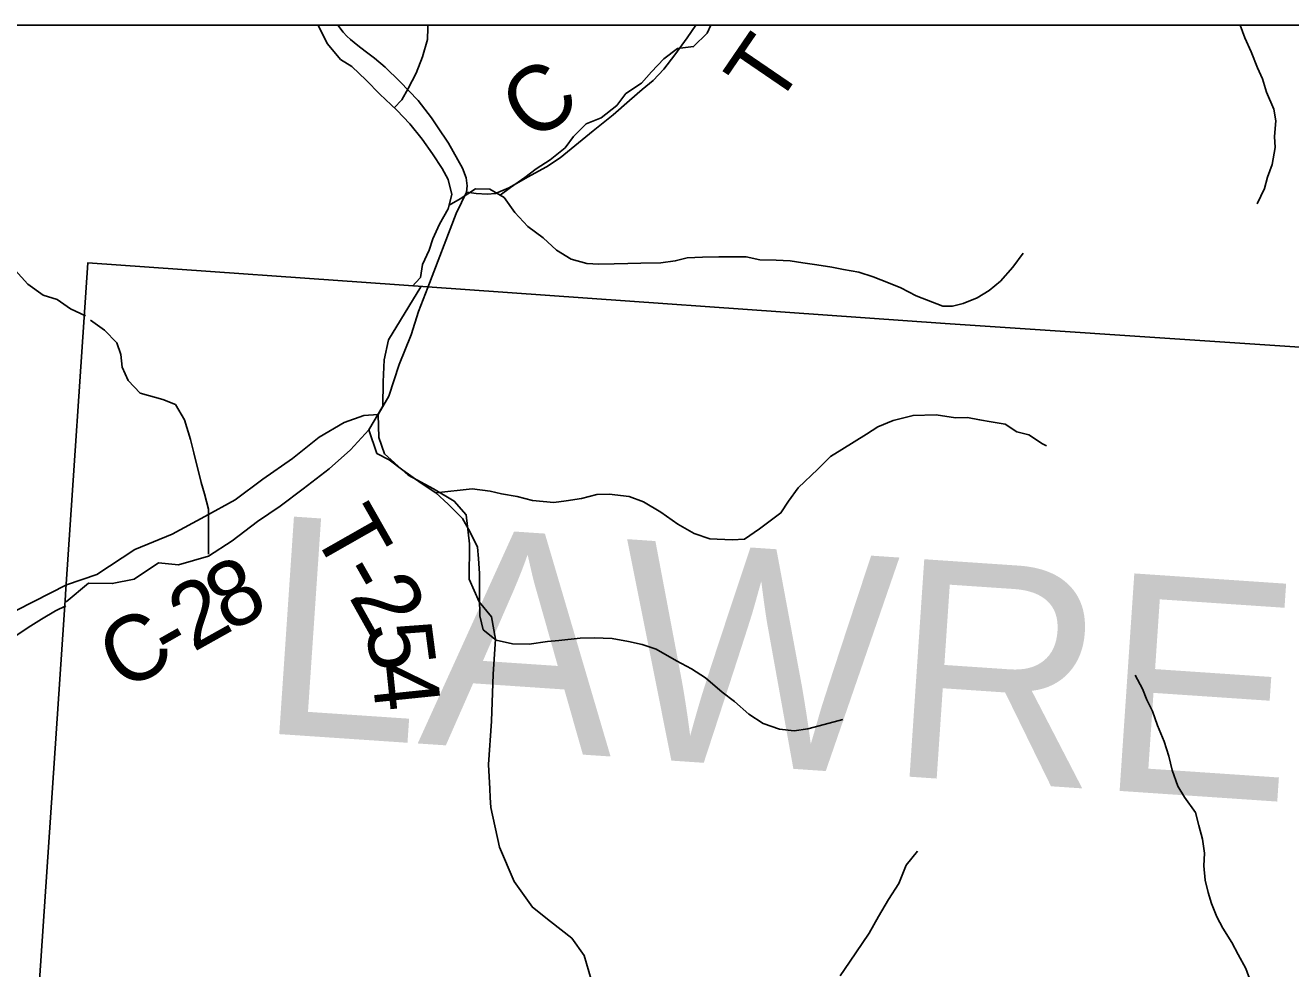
# Model space of a CAD drawing. Extents: x 0 to 34, y 0 to 22.
# Drawn here: x 3.511 to 4.61, y 20.08 to 20.9 of the extents above; entities that cross this region are included whole.
import ezdxf

# ---------------------------------------------------------------- set-up
doc = ezdxf.new("R2010")
doc.units = 0
for name, color, linetype in [('GM_X_County_Road', 7, 'Continuous'), ('GM_X_County_Road_Text', 7, 'Continuous'), ('GM_X_County_Text', 7, 'Continuous'), ('GM_X_Minor_River', 7, 'Continuous'), ('GM_X_Township_Road', 7, 'Continuous'), ('GM_X_Township_Road_Text', 7, 'Continuous'), ('GM_X_Unincorporated', 7, 'Continuous'), ('SH_Cut_Line', 7, 'Continuous')]:
    doc.layers.add(name, color=color, linetype=linetype)

msp = doc.modelspace()

# ---------------------------------------------------------------- linework, layer by layer
at = {"layer": 'GM_X_County_Road'}
for points in [[(3.8896, 20.746), (3.8941, 20.755), (3.8945, 20.7606), (3.8938, 20.7673), (3.8905, 20.7759), (3.8783, 20.7975), (3.8687, 20.8117), (3.8635, 20.8197), (3.852, 20.8345), (3.836, 20.8511), (3.8233, 20.8636), (3.8141, 20.8714), (3.8061, 20.8774), (3.7996, 20.8825), (3.7933, 20.8877), (3.79, 20.8906), (3.787, 20.894), (3.7822, 20.9)], [(3.8604, 20.6722), (3.885, 20.7363), (3.8896, 20.746)], [(3.5465, 20.4139), (3.573, 20.4229), (3.6059, 20.4444), (3.6382, 20.4578), (3.6668, 20.4731), (3.6931, 20.4877), (3.7171, 20.5057), (3.7427, 20.5237), (3.7659, 20.5421), (3.7877, 20.5548), (3.8048, 20.5608), (3.8173, 20.5618), (3.8265, 20.5777), (3.8355, 20.6053), (3.8459, 20.631), (3.8522, 20.6514), (3.8604, 20.6722)], [(3.4893, 20.3844), (3.5465, 20.4139)]]:
    msp.add_lwpolyline(points, dxfattribs=at)
at = {"layer": 'GM_X_Minor_River'}
for points in [[(3.8472, 20.6733), (3.8501, 20.6766), (3.8539, 20.6808), (3.8558, 20.6921), (3.8616, 20.7046), (3.8647, 20.7145), (3.8705, 20.7273), (3.8782, 20.7405), (3.8813, 20.753), (3.878, 20.7659), (3.8728, 20.7755), (3.8646, 20.7884), (3.8556, 20.801), (3.8447, 20.8144), (3.8334, 20.8262), (3.8188, 20.84), (3.8068, 20.8522), (3.7944, 20.8641), (3.7846, 20.8702), (3.7733, 20.884), (3.7681, 20.8939), (3.765, 20.9)], [(3.8313, 20.8282), (3.8377, 20.8353), (3.8434, 20.8451), (3.8504, 20.8583), (3.8558, 20.8727), (3.86, 20.8875), (3.8605, 20.8977), (3.8605, 20.9)], [(3.9232, 20.7524), (3.9321, 20.7591), (3.9446, 20.7677), (3.9545, 20.7752), (3.9667, 20.7831), (3.9797, 20.7936), (3.9869, 20.8034), (3.998, 20.8143), (4.0109, 20.8195), (4.0246, 20.8304), (4.0323, 20.8406), (4.046, 20.8496), (4.0548, 20.8594), (4.0654, 20.8707), (4.0773, 20.8797), (4.0913, 20.8815), (4.1031, 20.8931), (4.1063, 20.9)], [(4.566, 20.9), (4.5703, 20.8891), (4.5756, 20.8769), (4.5812, 20.8629), (4.5854, 20.8534), (4.5891, 20.842), (4.5955, 20.8271), (4.597, 20.8169), (4.5958, 20.8032), (4.5965, 20.7938), (4.5938, 20.779), (4.59, 20.768), (4.5873, 20.7581), (4.5808, 20.7449)], [(3.563, 20.6475), (3.5501, 20.6536), (3.5384, 20.6616), (3.5263, 20.6655), (3.5128, 20.6751), (3.5019, 20.6873), (3.4918, 20.6977), (3.479, 20.7114), (3.4707, 20.7213), (3.4602, 20.7339), (3.4516, 20.7469), (3.4396, 20.7584), (3.4318, 20.7706), (3.4311, 20.7827), (3.4312, 20.7956), (3.4309, 20.8059), (3.4321, 20.8165), (3.433, 20.8286), (3.4338, 20.8411)], [(3.879, 20.7436), (3.8885, 20.7492), (3.9018, 20.7578), (3.9143, 20.7577), (3.9267, 20.7504), (3.9361, 20.7374), (3.9473, 20.7252), (3.9605, 20.7152), (3.9721, 20.7045), (3.985, 20.6968), (3.9986, 20.6929), (4.0091, 20.6925), (4.0224, 20.6927), (4.0341, 20.693), (4.0455, 20.6933), (4.0629, 20.6935), (4.0754, 20.6953), (4.0857, 20.6979), (4.0989, 20.6986), (4.1133, 20.6988), (4.1371, 20.6987), (4.1489, 20.6963), (4.1629, 20.6958), (4.1753, 20.6953), (4.1863, 20.6937), (4.1984, 20.6917), (4.2113, 20.6897), (4.2215, 20.6878), (4.2347, 20.6854), (4.2472, 20.6815), (4.2607, 20.6761), (4.2713, 20.6718), (4.2845, 20.6649), (4.3077, 20.656)], [(4.3077, 20.656), (4.3161, 20.656), (4.3256, 20.6582), (4.3377, 20.6631), (4.348, 20.6695), (4.3579, 20.6775), (4.3685, 20.6899), (4.3776, 20.702)], [(3.5462, 20.399), (3.5657, 20.4151), (3.5862, 20.4149), (3.6052, 20.4186), (3.6265, 20.4329), (3.6439, 20.4312), (3.6698, 20.4386), (3.6903, 20.4521), (3.7124, 20.4687), (3.7322, 20.4822), (3.752, 20.4973), (3.7748, 20.5146), (3.7931, 20.5311), (3.8092, 20.5485), (3.8214, 20.5689), (3.8216, 20.5902), (3.8224, 20.6092), (3.8263, 20.6266), (3.8542, 20.6727)], [(3.5673, 20.6437), (3.5795, 20.6351), (3.5902, 20.6242), (3.5937, 20.614), (3.595, 20.603), (3.6, 20.5913), (3.6104, 20.5804), (3.6302, 20.5748), (3.6412, 20.5704), (3.649, 20.5572), (3.6541, 20.5401), (3.6572, 20.5284), (3.6635, 20.5026), (3.6663, 20.4928), (3.6698, 20.4795), (3.6698, 20.4404)], [(3.8674, 20.4936), (3.8989, 20.4973), (3.9145, 20.4952), (3.9244, 20.493), (3.9381, 20.4905), (3.9514, 20.4872), (3.97, 20.4854), (3.9806, 20.4867), (3.9939, 20.4887), (4.0071, 20.4923), (4.0178, 20.4927), (4.0352, 20.4906), (4.0478, 20.4858), (4.0627, 20.4768), (4.0776, 20.4664), (4.0917, 20.4585), (4.1054, 20.4537), (4.1248, 20.4528), (4.1354, 20.4536), (4.1486, 20.4625), (4.1671, 20.4763), (4.1738, 20.4866), (4.182, 20.4981), (4.1993, 20.5142), (4.2102, 20.5253), (4.22, 20.5315), (4.2415, 20.5446), (4.2514, 20.5512), (4.2646, 20.5566), (4.282, 20.561), (4.3021, 20.5615)], [(4.3021, 20.5615), (4.3188, 20.559), (4.3291, 20.5593), (4.3397, 20.5573), (4.3499, 20.5553), (4.362, 20.5534), (4.3722, 20.5468), (4.3824, 20.5441), (4.3944, 20.5364), (4.3978, 20.5345)], [(3.8092, 20.5485), (3.8162, 20.528), (3.8269, 20.5224), (3.8388, 20.5134), (3.8545, 20.5022), (3.8674, 20.4936), (3.8782, 20.4838), (3.8904, 20.4714), (3.897, 20.4601), (3.9036, 20.4465), (3.9044, 20.4366), (3.9053, 20.4237), (3.9054, 20.4127), (3.9052, 20.4024), (3.9057, 20.3869), (3.9085, 20.3747), (3.9199, 20.3657), (3.934, 20.3625), (3.9484, 20.3622), (3.9644, 20.3646), (3.9742, 20.3655), (3.9928, 20.3676), (4.0049, 20.3677), (4.0205, 20.3671), (4.0346, 20.3646), (4.0467, 20.362), (4.0589, 20.358), (4.0765, 20.3479), (4.0895, 20.3408), (4.1017, 20.3329), (4.1162, 20.3205), (4.1269, 20.3123), (4.1392, 20.3014), (4.1518, 20.2932), (4.1659, 20.2884), (4.1788, 20.287), (4.1906, 20.2886), (4.2046, 20.2925), (4.2208, 20.2969)], [(3.5009, 20.3684), (3.5131, 20.3766), (3.5249, 20.3841), (3.537, 20.3912), (3.5459, 20.3956)], [(4.4749, 20.3354), (4.4813, 20.3235), (4.485, 20.314), (4.4899, 20.3041), (4.4944, 20.2915), (4.5, 20.2778), (4.5041, 20.2649), (4.507, 20.2527), (4.5119, 20.2389), (4.5179, 20.2294), (4.5273, 20.216), (4.5303, 20.2046), (4.5333, 20.1928), (4.5351, 20.1806), (4.5346, 20.1696), (4.5357, 20.1571), (4.5383, 20.1464), (4.5412, 20.1369), (4.5457, 20.1254), (4.551, 20.1155), (4.5589, 20.1029), (4.5645, 20.0926), (4.5709, 20.0804), (4.5754, 20.0686)], [(4.2857, 20.1824), (4.276, 20.1702), (4.2697, 20.1542), (4.2607, 20.1404), (4.2518, 20.1255), (4.2439, 20.111), (4.2267, 20.0858), (4.2185, 20.074)]]:
    msp.add_lwpolyline(points, dxfattribs=at)
at = {"layer": 'GM_X_Township_Road'}
for points in [[(3.9416, 20.7649), (3.9469, 20.768), (3.9635, 20.7769), (3.9753, 20.7849), (4.0041, 20.8084), (4.0214, 20.8222), (4.0356, 20.8347), (4.0467, 20.8443), (4.0563, 20.852), (4.0653, 20.8618), (4.0751, 20.8743), (4.0857, 20.8891), (4.0933, 20.9)], [(3.8941, 20.755), (3.9023, 20.7538), (3.9119, 20.7533), (3.9192, 20.7538), (3.9309, 20.7588), (3.9416, 20.7649)], [(3.8173, 20.5618), (3.8179, 20.5417), (3.8227, 20.5276), (3.8434, 20.5092), (3.8652, 20.4972), (3.8833, 20.4865), (3.8938, 20.4746), (3.8967, 20.4495), (3.8964, 20.4188), (3.9049, 20.399), (3.9158, 20.386), (3.9191, 20.3666), (3.9173, 20.3363), (3.9158, 20.2953), (3.9132, 20.2577), (3.9143, 20.2366), (3.9147, 20.2291)], [(3.9147, 20.2291), (3.9151, 20.2202), (3.9228, 20.1859), (3.9354, 20.1559), (3.9512, 20.1337), (3.967, 20.1214), (3.9854, 20.1069), (3.9963, 20.0916), (4.0065, 20.0569), (4.0146, 20.0404), (4.0196, 20.03)]]:
    msp.add_lwpolyline(points, dxfattribs=at)
at = {"layer": 'GM_X_Unincorporated'}
msp.add_lwpolyline([(6.769, 20.9), (2.2853, 20.9), (2.418, 20.5866), (2.7473, 19.8121), (2.9553, 19.318), (2.9956, 19.2227), (3.0781, 19.0279), (3.1249, 18.9173), (3.4011, 18.2653), (3.4595, 19.1305), (3.4599, 19.1361), (3.5099, 19.8769), (3.5456, 20.4047), (3.5457, 20.4056), (3.5462, 20.4144), (3.5651, 20.6937), (3.8602, 20.6728), (4.3099, 20.6409), (6.6484, 20.4847), (6.6568, 20.5136)], close=True, dxfattribs=at)
msp.add_lwpolyline([(8.9, 14.2264), (8.9, 20.3234), (8.6245, 20.3436), (7.6038, 20.4229), (7.3955, 20.4364), (6.962, 20.4644), (6.8381, 20.4724), (6.7584, 20.4776), (6.6718, 20.4832), (6.6484, 20.4847), (4.3099, 20.6409), (3.8602, 20.6728), (3.5651, 20.6937), (3.5462, 20.4144), (3.5457, 20.4056), (3.5456, 20.4047), (3.5099, 19.8769)], dxfattribs=at)
at = {"layer": 'SH_Cut_Line'}
for points in [[(4.2937, 16.1161), (4.0882, 16.6114), (3.972, 16.8916), (3.7367, 17.4136), (3.709, 17.484), (3.4011, 18.2653), (3.4595, 19.1305), (3.4599, 19.1361), (3.5099, 19.8769), (3.5456, 20.4047), (3.5457, 20.4056), (3.5462, 20.4144), (3.5651, 20.6937), (3.8602, 20.6728), (4.3099, 20.6409), (6.6484, 20.4847), (6.6568, 20.5136), (6.769, 20.9), (2.1, 20.9), (2.1, 14.1)], [(8.9, 14.1), (8.9, 20.9), (6.769, 20.9), (6.6568, 20.5136), (6.6484, 20.4847), (4.3099, 20.6409), (3.8602, 20.6728), (3.5651, 20.6937), (3.5462, 20.4144), (3.5457, 20.4056), (3.5456, 20.4047), (3.5099, 19.8769), (3.4599, 19.1361), (3.4595, 19.1305), (3.4011, 18.2653), (3.709, 17.484), (3.7367, 17.4136), (3.972, 16.8916), (4.0882, 16.6114), (4.2937, 16.1161)]]:
    msp.add_lwpolyline(points, dxfattribs=at)

# ---------------------------------------------------------------- texts
at = {"layer": 'GM_X_County_Road_Text'}
for s, rotation, p in [('8', 27.9289, (3.6869, 20.3719)), ('2', 29.2517, (3.6566, 20.3549)), ('C', 29.6246, (3.5959, 20.3204)), ('-', 29.5546, (3.6364, 20.3435))]:
    msp.add_text(s, height=0.0568, rotation=rotation, dxfattribs=at).set_placement(p)
at = {"layer": 'GM_X_County_Text'}
msp.add_text('LAWRENCE COUNTY', height=0.189394, rotation=356.1322, dxfattribs=at).set_placement((3.7106, 20.2855))
at = {"layer": 'GM_X_Township_Road_Text'}
for s, rotation, p in [('T', 55.6835, (4.1623, 20.8267)), ('C', 38.0752, (3.9526, 20.7967)), ('T', 299.6311, (3.7588, 20.4608)), ('-', 299.6035, (3.7798, 20.4239)), ('2', 299.2634, (3.7913, 20.4036)), ('5', 277.4155, (3.8066, 20.3785)), ('4', 275.9118, (3.8111, 20.3442))]:
    msp.add_text(s, height=0.0568, rotation=rotation, dxfattribs=at).set_placement(p)

doc.saveas('drawing.dxf')
